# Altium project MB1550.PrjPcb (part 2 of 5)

## Sheet BOARD_PWR.SchDoc: BOARD PWR
size A4; Date: Not used; ApprovedBy: Not used; CheckedBy: Not used; Author: Not used; CompanyName: STMicroelectronics; DrawnBy: Not used; Engineer: Not used; Organization: Not used; Address1: Not used; Address2: Not used; Address3: Not used; Address4: Not used; DocumentNumber: 21; Revision: Not used; SheetNumber: 21; SheetTotal: 24
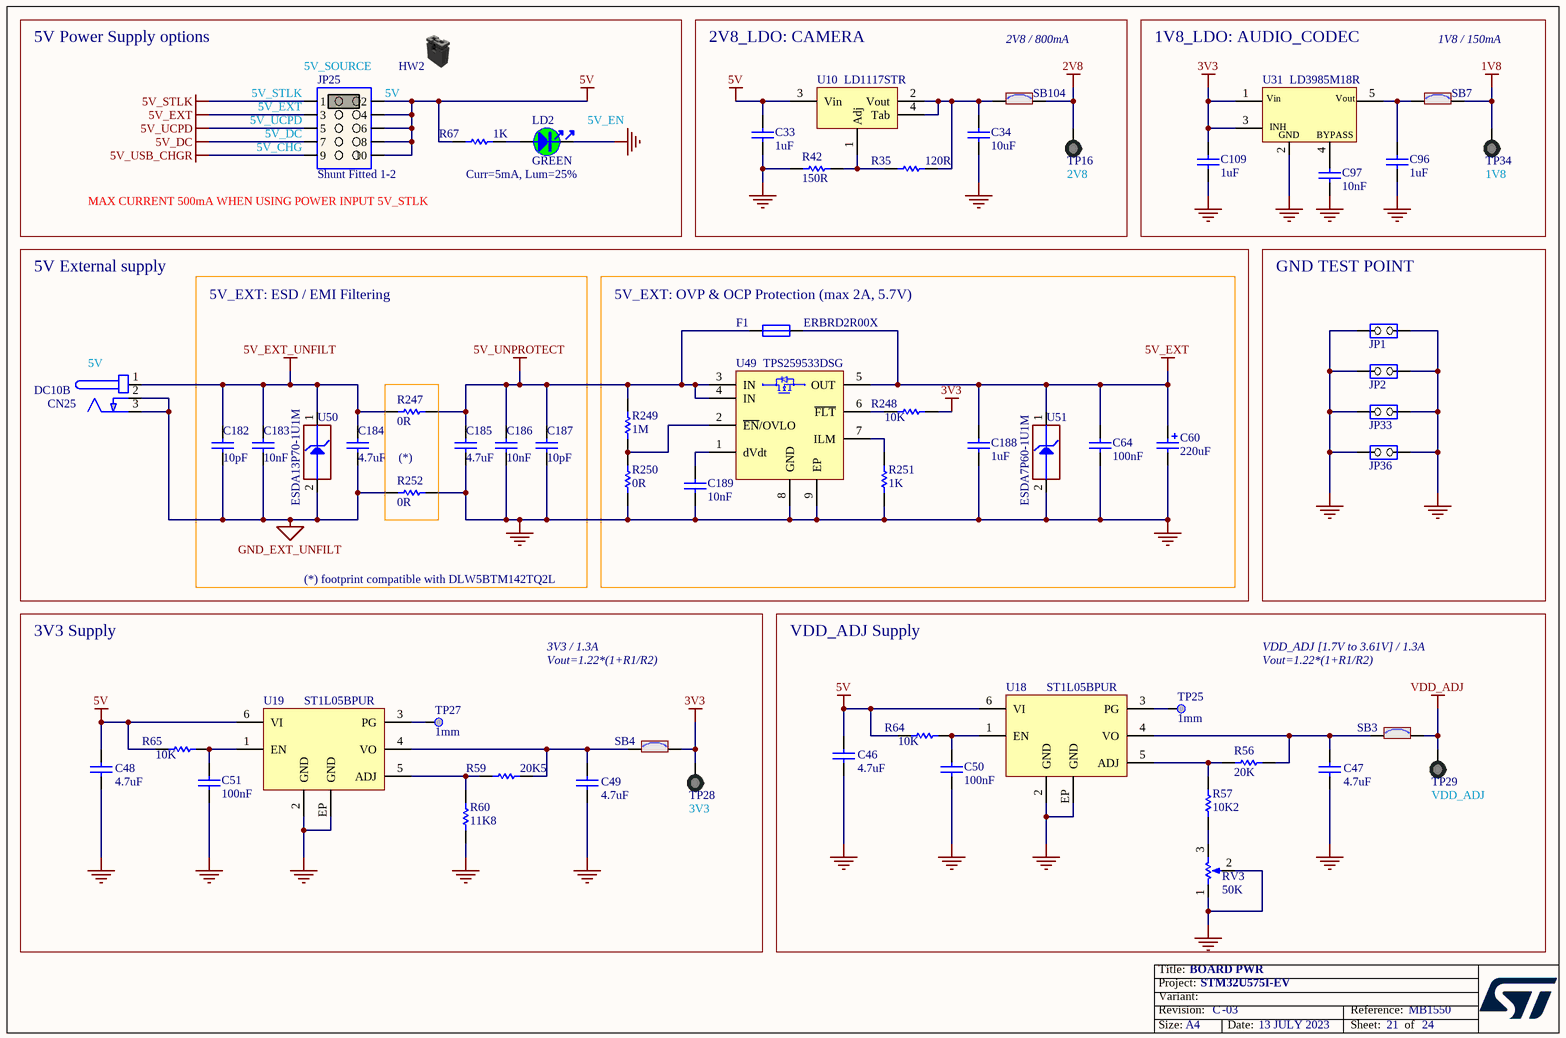
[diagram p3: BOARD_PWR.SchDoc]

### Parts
C33  value 1uF  [C0603]
C34  value 10uF  [C0402]  (hidden comment: Capacitor)
C46  value 4.7uF  [C0603]
C47  value 4.7uF  [C0603]
C48  value 4.7uF  [C0603]
C49  value 4.7uF  [C0603]
C50  value 100nF  [C0402]
C51  value 100nF  [C0402]
C60  value 220uF  [CPOL_TAJ-C_2312_H2P6]
C64  value 100nF  [C0402]
C96  value 1uF  [C0603]
C97  value 10nF  [C0402]
C109  value 1uF  [C0603]
C182  value 10pF  [C0402]  (hidden comment: Capacitor)
C183  value 10nF  [C0402]  (hidden comment: Capacitor)
C184  value 4.7uF  [C0603]  (hidden comment: Capacitor)
C185  value 4.7uF  [C0603]  (hidden comment: Capacitor)
C186  value 10nF  [C0402]  (hidden comment: Capacitor)
C187  value 10pF  [C0402]  (hidden comment: Capacitor)
C188  value 1uF  [C0603]
C189  value 10nF  [C0402]  (hidden comment: Capacitor)
CN25  value DC10B  [CON_DC-POWER-SOCKET_CLIFF_FC68149_DC10B]
F1  value ERBRD2R00X  [PTC_Panasonic_micro_chip_fuse_0402]  (hidden comment: FUSE)
HW2  (no value)  (mechanical)
JP1  Jumper_Header 2x1  [CON_SAMTEC_TSW-102-07-G-S]  (value not drawn)
JP2  Jumper_Header 2x1  [CON_SAMTEC_TSW-102-07-G-S]  (value not drawn)
JP25  value Shunt Fitted 1-2  [CON_SAMTEC_TSW-105-07-X-D]
JP33  Jumper_Header 2x1  [CON_SAMTEC_TSW-102-07-G-S]  (value not drawn)
JP36  Jumper_Header 2x1  [CON_SAMTEC_TSW-102-07-G-S]  (value not drawn)
LD2  value GREEN  [LED_0603_OSRAM_LG-Q396-PS-35_GREEN_1A2K_H0P4]
R35  value 120R  [R0603]  (hidden comment: Resistor)
R42  value 150R  [R0603]
R56  value 20K  [R0603]
R57  value 10K2  [R0603]
R59  value 20K5  [R0603]
R60  value 11K8  [R0603]
R64  value 10K  [R0603]
R65  value 10K  [R0603]
R67  value 1K  [R0603]  (hidden comment: Resistor)
R247  value 0R  [R0805]  (hidden comment: Resistor)
R248  value 10K  [R0603]
R249  value 1M  [R0402]  (hidden comment: Resistor)
R250  value 0R  [R0402]  (hidden comment: Resistor)
R251  value 1K  [R0603]  (hidden comment: Resistor)
R252  value 0R  [R0805]  (hidden comment: Resistor)
RV3  value 50K  [POT_BOURNS_3386P]  (hidden comment: POTENTIOMETER)
SB3  (no value)  [SOLDER-BRIDGE_R0603-0R]
SB4  (no value)  [SOLDER-BRIDGE_R0603-0R]
SB7  (no value)  [SOLDER-BRIDGE_R0603-0R]
SB104  (no value)  [SOLDER-BRIDGE_R0603-0R]
TP16  value 2V8  [TP_PTH_1MM_2MM]  (no BOM)
TP25  value 1mm  [TP_SMD_1MM]  (no BOM)
TP27  value 1mm  [TP_SMD_1MM]  (no BOM)
TP28  value 3V3  [TP_PTH_1MM_2MM]  (no BOM)
TP29  value VDD_ADJ  [TP_PTH_1MM_2MM]  (no BOM)
TP34  value 1V8  [TP_PTH_1MM_2MM]  (no BOM)
U10  value LD1117STR  [REG_SOT223-TAB]
U18  value ST1L05BPUR  [ICC_DFN6-EPAD_3X3_P095]
U19  value ST1L05BPUR  [ICC_DFN6-EPAD_3X3_P095]
U31  value LD3985M18R  [REG_SOT23-5L]
U49  TPS259533DSG  [ICC_WSON8-EPAD_2X2_P050]
U50  value ESDA13P70-1U1M  [ESD_QFN1610_2N_1K_2A]  (hidden comment: ESD-TRANSIL)
U51  value ESDA7P60-1U1M  [ESD_QFN2_1P6X1_P125]  (hidden comment: ESD-TRANSIL)

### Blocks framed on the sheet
5V Power Supply options: HW2 JP25 LD2 R67
2V8_LDO: CAMERA: C33 C34 R35 R42 SB104 TP16 U10
1V8_LDO: AUDIO_CODEC: C96 C97 C109 SB7 TP34 U31
5V External supply: CN25
5V_EXT: ESD / EMI Filtering: C182-C187 U50
5V_EXT: OVP & OCP Protection (max 2A, 5.7V): C60 C64 C188 C189 F1 R248-R251 U49 U51
GND TEST POINT: JP1 JP2 JP33 JP36
(*): R247 R252
3V3 Supply: C48 C49 C51 R59 R60 R65 SB4 TP27 TP28 U19
VDD_ADJ Supply: C46 C47 C50 R56 R57 R64 RV3 SB3 TP25 TP29 U18

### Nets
1V8: SB7.2 TP34.1
2V8: SB104.2 TP16.1
3V3: C109.2 R248.2 SB4.2 TP28.1 U31.1(Vin) U31.3(CE)
5V: C33.2 C46.2 C48.2 JP25.2 JP25.4 JP25.6 JP25.8 JP25.10 R64.1 R65.1 R67.1 U10.3(Vin) U18.6(VI) U19.6(VI)
5V_DC: JP25.7
5V_EXT: C60.1 C64.1 C188.2 F1.2 JP25.3 U49.5(OUT) U51.1(IO1)
5V_EXT_UNFILT: C182.2 C183.2 C184.2 CN25.1 R247.1 U50.1(IO1)
5V_STLK: JP25.1
5V_UCPD: JP25.5
5V_UNPROTECT: C185.2 C186.2 C187.2 F1.1 R247.2 R249.2 U49.3(IN) U49.4(IN)
5V_USB_CHGR: JP25.9
GND: C33.1 C34.1 C46.1 C47.1 C48.1 C49.1 C50.2 C51.2 C60.2 C64.2 C96.1 C97.1 C109.1 C185.1 C186.1 C187.1 C188.1 C189.1 JP1.1(COMMON) JP1.2(NO) JP2.1(COMMON) JP2.2(NO) JP33.1(COMMON) JP33.2(NO) JP36.1(COMMON) JP36.2(NO) LD2.2 R42.1 R60.1 R250.1 R251.1 R252.2 RV3.1(BOT) RV3.2(TAP) U18.2(GND) U18.EP(GND) U19.2(GND) U19.EP(GND) U31.2(GND) U49.8(GND) U49.9(EP) U51.2(GND)
GND_EXT_UNFILT: C182.1 C183.1 C184.1 CN25.2 CN25.3 R252.1 U50.2(GND)
VDD_ADJ: SB3.2 TP29.1
NetC34_2: C34.2 R35.2 SB104.1 U10.2(Vout) U10.4(Tab)
NetC47_2: C47.2 R56.2 SB3.1 U18.4(VO)
NetC49_2: C49.2 R59.2 SB4.1 U19.4(VO)
NetC50_1: C50.1 R64.2 U18.1(EN)
NetC51_1: C51.1 R65.2 U19.1(EN)
NetC96_2: C96.2 SB7.1 U31.5(Vout)
NetC97_2: C97.2 U31.4(BYPASS)
NetC189_2: C189.2 U49.1(dVdt)
NetLD2_1: LD2.1 R67.2
NetR35_1: R35.1 R42.2 U10.1(Adj)
NetR56_1: R56.1 R57.2 U18.5(ADJ)
NetR57_1: R57.1 RV3.3(TOP)
NetR59_1: R59.1 R60.2 U19.5(ADJ)
NetR248_1: R248.1 U49.6(~{FLT})
NetR249_1: R249.1 R250.2 U49.2(~{EN}/OVLO)
NetR251_2: R251.2 U49.7(ILM)
NetTP25_1: TP25.1 U18.3(PG)
NetTP27_1: TP27.1 U19.3(PG)

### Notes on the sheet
- 2V8 / 800mA
- 1V8 / 150mA
- (near JP25) 5V_STLK
- (near JP25) 5V_EXT
- (near JP25) 5V_SOURCE
- (near JP25) 5V
- (near JP25) 5V_UCPD
- (near JP25) 5V_CHG
- (near JP25) 5V_DC
- Curr=5mA, Lum=25%
- (near LD2) 5V_EN
- (near JP25) MAX CURRENT 500mA WHEN USING POWER INPUT 5V_STLK
- (near CN25) 5V
- (*) footprint compatible with DLW5BTM142TQ2L
- 3V3 / 1.3A
- VDD_ADJ [1.7V to 3.61V] / 1.3A
- Vout=1.22*(1+R1/R2)

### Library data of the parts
C33 C96 C109 C188 = MCD-00010: Capacitor, MLCC, 1uF, 16V, X5R, 10%, 0603, T=0,8mm; Manufacturer_Part_Number: CC0603KRX5R7BB105; Manufacturer: YAGEO; Provided_By: Subcon; Initial_Board_Reference: MB1274
C34 = MCD-01355: Capacitor, MLCC, 10uF, 4V, X5R, 20%, 0402, T=0,5mm; Manufacturer_Part_Number: GRM155R60G106ME44; Manufacturer: MURATA; ECCN_US: EAR99; ECCN_EU: NEC; Provided_By: Subcon; Initial_Board_Reference: MB1372
C46-C49 = MCD-00009: Capacitor, MLCC, 4.7uF, 16V, X5R, 10%, 0603, T=0.8mm; Manufacturer_Part_Number: CC0603KRX5R7BB475; Manufacturer: YAGEO; ECCN_US: EAR99; ECCN_EU: NEC; Provided_By: SUBCO
C50 C51 C64 = MCD-00006: Capacitor, MLCC, 100nF, 16V, X7R, 10%, 0402, T=0.5mm; Manufacturer_Part_Number: CC0402KRX7R7BB104; Manufacturer: YAGEO; Alternate_Manufacturer_Part_Number: GCM155R71C104KA55D; Alternate_Manufacturer: MURATA; Provided_By: SUBCO; ECCN_US: EAR99; ECCN_EU: NEC
C60 = MCD-00142: Capacitor, Tantalum, 220uF, 10V, 10%, TypeC; Manufacturer_Part_Number: TAJC227K010R; Manufacturer: AVX; Provided_By: Subcon; ECCN_US: EAR99; ECCN_EU: NEC; Initial_Board_Reference: MB1262
C97 = MCD-00011: Capacitor, MLCC, 10nF, 16V, X7R, 10%, 0402, T=0.5mm; Manufacturer_Part_Number: CC0402KRX7R7BB103; Manufacturer: YAGEO; Provided_By: Subcon; Initial_Board_Reference: MB1274
C182 C187 = MCD-00015: Capacitor, MLCC, 10pF, 50V, NPO, +/-5%, 0402, T=0,5mm; Manufacturer_Part_Number: CC0402JRNPO9BN100; Manufacturer: YAGEO; Part_Preference: Recommended
C183 C186 = MCD-02198: Capacitor, MLCC, 10nF, 50V ,X7R, +/-10%, 0402, T=0.5mm; Manufacturer_Part_Number: CC0402KRX7R9BB103; Manufacturer: YAGEO; Alternate_Manufacturer_Part_Number: UMF105B7103KVHF; Alternate_Manufacturer: TAIYO YUDEN; Part_Preference: Recommended; Order_Code_RS: 6169644
C184 C185 = MCD-02196: Capacitor, MLCC, 4.7uF, 25V, X5R, +/-10%, 0603, T=0,8mm; Manufacturer_Part_Number: C1608X5R1E475K080AC; Manufacturer: TDK; Alternate_Manufacturer_Part_Number: TMK107BBJ475KA-T; Alternate_Manufacturer: TAIYO YUDEN; Part_Preference: Recommended; Order_Code_RS: 9159158
C189 = MCD-00011: Capacitor, MLCC, 10nF, 16V, X7R, +/-10%, 0402, T=0.5mm; Manufacturer_Part_Number: CC0402KRX7R7BB103; Manufacturer: YAGEO; Part_Preference: Recommended; Order_Code_RS: 669-8688
CN25 = MCD-00173: DC-Power-Jack, 2.5mm, 5A, RA, TH; Manufacturer: CLIFF; Part_Type: Connector; Provided_By: Subcon; Initial_Board_Reference: MB1265
F1 = MCD-02197: Micro Chip Fuse, Fast Acting, 2A, 53mOhm, 32V Rated Voltage; Part_Type: Misc; Manufacturer: PANASONIC; Part_Preference: Recommended; Order_Code_RS: 7594751
HW2 = MCD-00043: SHUNT 2.54mm BLACK; Part_Type: Mechanical; Manufacturer_Part_Number: SNT-100-BK-G; Manufacturer: SAMTEC; Provided_By: Subcon; Initial_Board_Reference: MB1274
JP1 JP2 JP33 JP36 = MCD-00045: Header, 2x1, 2,54mm, VR, TH, Height 5.84mm/2.54mm; Part_Type: Connector; Manufacturer_Part_Number: TSW-102-07-x-S; Manufacturer: SAMTEC; Value: Shunt not fitted; Provided_By: Subcon; Initial_Board_Reference: MB1274; Remark: 3D KO: BZ: 40098
JP25 = MCD-01203: Header, 5x2, 2,54mm, VR, TH, Height 5.84mm/2.54mm - Shunt Fitted 1-2; Part_Type: Connector; Manufacturer_Part_Number: TSW-105-07-x-D; Manufacturer: SAMTEC; Provided_By: Subcon; Initial_Board_Reference: Mb1372
LD2 = MCD-00588: LED Green, 0603 SMD, Forward Voltage Typ=2V, Max=2.5V; Part_Type: Display; Manufacturer_Part_Number: LG Q396-PS-35; Manufacturer: OSRAM OPTO SEMICONDUCTORS; Alternate_Manufacturer_Part_Number: VLMTG1300-GS08; Alternate_Manufacturer: VISHAY SEMICONDUCTOR OPTO DIVISION; Provided_By: Subcon; Initial_Board_Reference: MB1331
R35 = MCD-00338: Resistor,120R,0603,1%,1/10W; Manufacturer_Part_Number: RC0603FR-07120RL; Manufacturer: YAGEO; BMS_Part_Number: 9129734; ECCN_US: EAR99; ECCN_EU: NEC; Provided_By: SUBCO
R42 = MCD-00394: Resistor,150,0603,1%,1/10W; Manufacturer_Part_Number: RC0603FR-07150RL; Manufacturer: YAGEO; ECCN_US: EAR99; ECCN_EU: NEC; Provided_By: SUBCO
R56 = MCD-00422: Resistor,20K,0603,1%,1/10W; Manufacturer_Part_Number: RC0603FR-0720KL; Manufacturer: YAGEO; Provided_By: Subcon
R57 = MCD-01155: Resistor,10K2,0603,1%,1/10W; Manufacturer_Part_Number: RC0603FR-0710K2L; Manufacturer: YAGEO; Provided_By: Subcon; Initial_Board_Reference: MB1372
R59 = MCD-01149: Resistor,20K5,0603,1%,1/10W; Manufacturer_Part_Number: RC0603FR-0720K5L; Manufacturer: YAGEO; Provided_By: Subcon; Initial_Board_Reference: MB1372
R60 = MCD-00244: Resistor,11K8,0603,1%,1/10W; Manufacturer_Part_Number: RC0603FR-0711K8L; Manufacturer: YAGEO; Provided_By: Subcon; Initial_Board_Reference: MB1319
R64 R65 R248 = MCD-00220: Resistor,10K,0603,1%,1/10W; Manufacturer_Part_Number: RC0603FR-0710KL; Manufacturer: YAGEO; Provided_By: Subcon; Initial_Board_Reference: MB1319
R67 R251 = MCD-00070: Resistor,1K,0603,1%,1/10W; Manufacturer_Part_Number: RC0603FR-071KL; Manufacturer: YAGEO; ECCN_US: EAR99; ECCN_EU: NEC; Provided_By: SUBCO
R247 R252 = MCD-00179: Resistor,0R,0805,5%?1/8W; Manufacturer_Part_Number: RC0805JR-070RL; Manufacturer: YAGEO; Part_Preference: Recommended
R249 = MCD-00182: Resistor,1M,0402,1%,1/16W; Manufacturer_Part_Number: RC0402FR-071ML; Manufacturer: YAGEO; BMS_Part_Number: 9131778; Part_Preference: Recommended; Order_Code_RS: 618-6194
R250 = MCD-00052: Resistor,0R,0402,5%,1/16W; Manufacturer_Part_Number: RC0402JR-070RL; Manufacturer: YAGEO; Part_Preference: Recommended; Order_Code_RS: 618-5804
RV3 = MCD-01156: Trimmer, 50K, 3386P, +/-10%, 1/2W, T=10.41mm; Part_Type: Resistor; Manufacturer_Part_Number: 3386P-1-503TLF; Manufacturer: BOURNS; Part_Preference: Recommended; Order_Code_RS: 167-3478
SB3 SB4 SB7 SB104 = MCD-00071: Solder Bridge ON; Part_Type: Mechanical; Provided_By: Subcon; Initial_Board_Reference: MB1274
TP16 TP28 TP29 TP34 = MCD-01506: Test Point trought hole 1mm/2mm; Part_Type: Mechanical; Initial_Board_Reference: MB1372; Item Type: Item; Path: ws/MCD_ApplicationBoards/Lists/MCDPARTSdatabase
TP25 TP27 = MCD-00074: Test Point 1mm; Part_Type: Mechanical; Initial_Board_Reference: MB1274
U10 = MCD-00721: LDO Voltage Regulator, Adjustable, 15V in, 1.1V drop, 1.25V to 15V/0.8A out, SOT-223-3; Part_Type: IC; Manufacturer: STMICROELECTRONICS; BMS_Part_Number: 9176132; ECCN_US: EAR99; ECCN_EU: NEC; Provided_By: SUBCO with ST control
U18 U19 = MCD-00581: LDO Linear Voltage Regulator IC Positive Adjustable 1 Output Adjustable 1.3A 6-DFN (3x3); Manufacturer: STMICROELECTRONICS; ECCN_US: EAR99; ECCN_EU: NEC; Provided_By: Subcon; Initial_Board_Reference: MB1331
U31 = MCD-00078: Ultra low drop-low noise BiCMOS voltage, regulators low ESR capacitors compatible; Manufacturer: STMICROELECTRONICS; Part_Type: IC; ECCN_US: EAR99; ECCN_EU: NEC; Provided_By: Subcon; Initial_Board_Reference: MB1274
U49 = MCD-02194: eFuse with Fast Overvoltage Protection 2.7V to 18V 4A 34mOhm 8-Pin WSON; Part_Type: IC; Manufacturer_Part_Number: TPS259533DSGR; Manufacturer: TEXAS INSTRUMENTS; Alternate_Manufacturer_Part_Number: TPS259533DSGT; Part_Preference: Recommended
U50 = MCD-02195: Diode, High power transient voltage suppressor, 13V breakdown; Manufacturer: STMICROELECTRONICS; Manufacturer_HQ_COO: EU; Part_Preference: Recommended; Order_Code_RS: 1106380
U51 = MCD-00251: High power transient voltage suppressor, 7V breakdown; Part_Type: Diode; Manufacturer: STMICROELECTRONICS; BMS_Part_Number: 9179042; Manufacturer_HQ_COO: EU; Part_Preference: Recommended

## Sheet Extension_Connector.SchDoc: EXTENSION CONNECTORS
size A4; Date: Not used; ApprovedBy: Not used; CheckedBy: Not used; Author: Not used; CompanyName: STMicroelectronics; DrawnBy: Not used; Engineer: Not used; Organization: Not used; Address1: Not used; Address2: Not used; Address3: Not used; Address4: Not used; DocumentNumber: 24; Revision: Not used; SheetNumber: 24; SheetTotal: 24
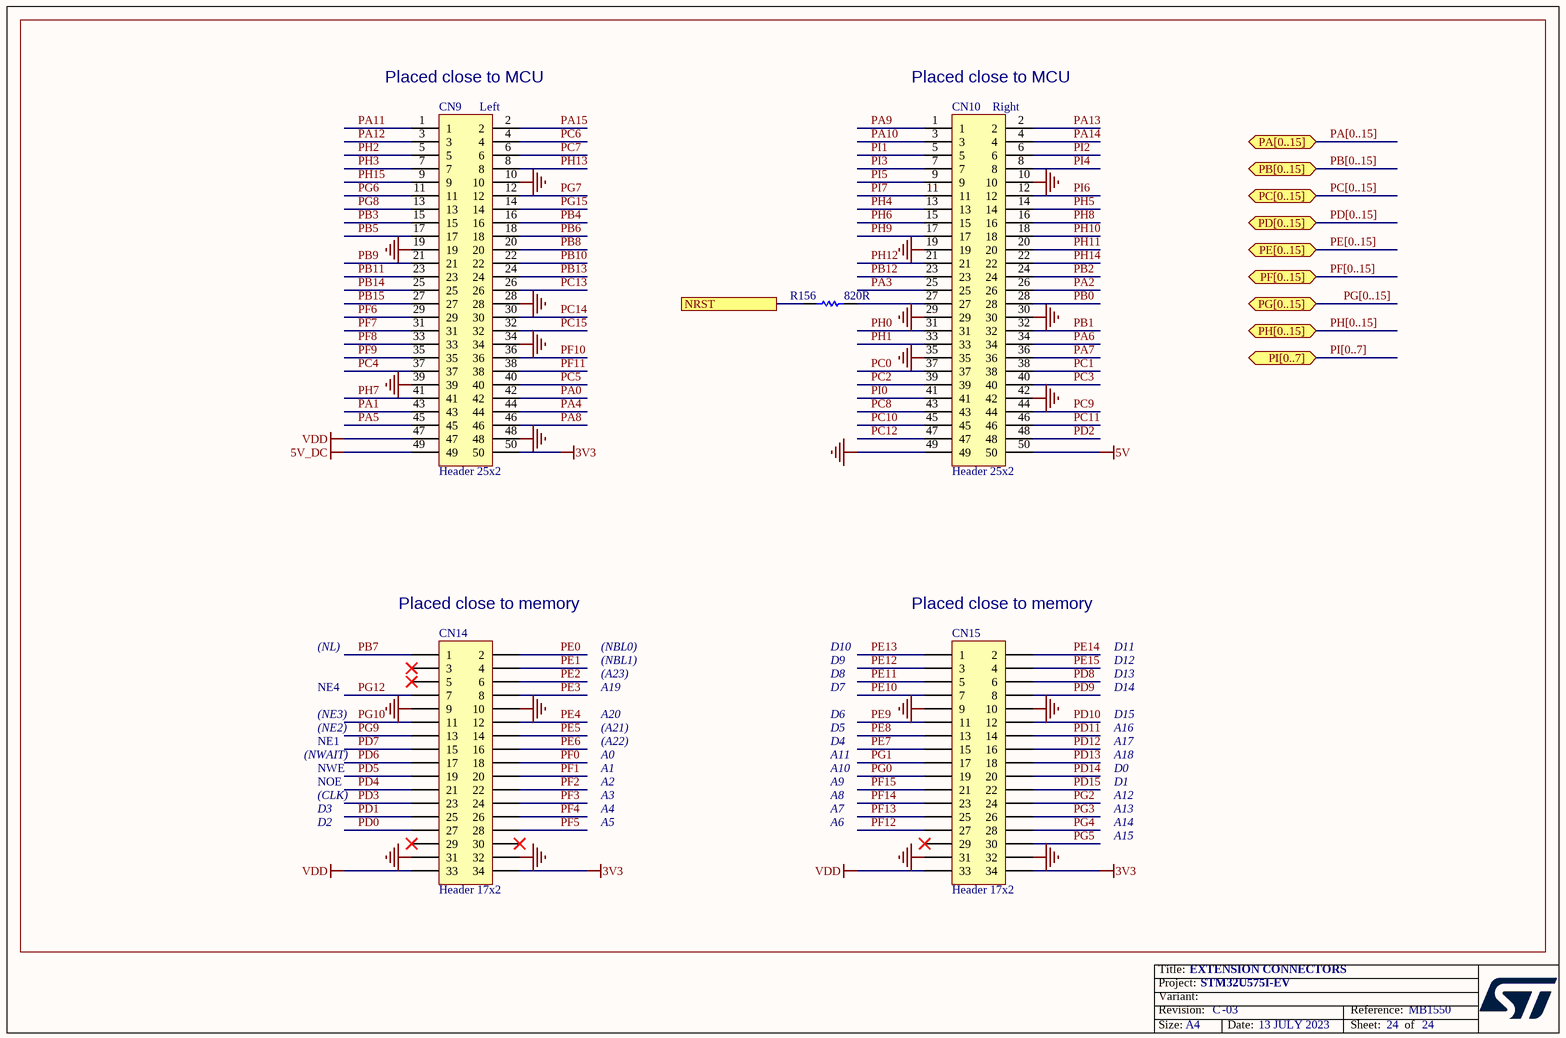
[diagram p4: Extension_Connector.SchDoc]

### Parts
CN9  Header 25x2  [CON_SAMTEC_FTR-125-03-L-D-LC]
CN10  Header 25x2  [CON_SAMTEC_FTR-125-03-L-D-LC]
CN14  Header 17x2  [CON_SAMTEC_FTR-117-03-L-D-LC]
CN15  Header 17x2  [CON_SAMTEC_FTR-117-03-L-D-LC]
R156  value 820R  [R0603]

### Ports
NRST, PA[0..15] (bidir), PB[0..15] (bidir), PC[0..15] (bidir), PD[0..15] (bidir), PE[0..15] (bidir), PF[0..15] (bidir), PG[0..15] (bidir), PH[0..15] (bidir), PI[0..7] (bidir)

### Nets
3V3: CN9.50 CN14.34 CN15.34
5V: CN10.50
5V_DC: CN9.49
GND: CN9.10 CN9.19 CN9.28 CN9.34 CN9.39 CN9.48 CN10.10 CN10.19 CN10.29 CN10.30 CN10.35 CN10.42 CN10.49 CN14.9 CN14.10 CN14.31 CN14.32 CN15.9 CN15.10 CN15.31 CN15.32
VDD: CN9.47 CN14.33 CN15.33
NRST: R156.1 ; port NRST
PA0: CN9.42
PA1: CN9.43
PA2: CN10.26
PA3: CN10.25
PA4: CN9.44
PA5: CN9.45
PA6: CN10.34
PA7: CN10.36
PA8: CN9.46
PA9: CN10.1
PA10: CN10.3
PA11: CN9.1
PA12: CN9.3
PA13: CN10.2  [project net JTMS_SWDIO]
PA14: CN10.4  [project net JTCK_SWCLK]
PA15: CN9.2
PB0: CN10.28
PB1: CN10.32
PB2: CN10.24
PB3: CN9.15
PB4: CN9.16
PB5: CN9.17
PB6: CN9.18
PB7: CN14.1
PB8: CN9.20
PB9: CN9.21
PB10: CN9.22
PB11: CN9.23
PB12: CN10.23
PB13: CN9.24
PB14: CN9.25
PB15: CN9.27
PC0: CN10.37
PC1: CN10.38
PC2: CN10.39
PC3: CN10.40
PC4: CN9.37
PC5: CN9.40
PC6: CN9.4
PC7: CN9.6
PC8: CN10.43
PC9: CN10.44
PC10: CN10.45
PC11: CN10.46
PC12: CN10.47
PC13: CN9.26
PC14: CN9.30
PC15: CN9.32
PD0: CN14.27
PD1: CN14.25
PD2: CN10.48
PD3: CN14.23
PD4: CN14.21
PD5: CN14.19
PD6: CN14.17
PD7: CN14.15
PD8: CN15.6
PD9: CN15.8
PD10: CN15.12
PD11: CN15.14
PD12: CN15.16
PD13: CN15.18
PD14: CN15.20
PD15: CN15.22
PE0: CN14.2
PE1: CN14.4
PE2: CN14.6
PE3: CN14.8
PE4: CN14.12
PE5: CN14.14
PE6: CN14.16
PE7: CN15.15
PE8: CN15.13
PE9: CN15.11
PE10: CN15.7
PE11: CN15.5
PE12: CN15.3
PE13: CN15.1
PE14: CN15.2
PE15: CN15.4
PF0: CN14.18
PF1: CN14.20
PF2: CN14.22
PF3: CN14.24
PF4: CN14.26
PF5: CN14.28
PF6: CN9.29
PF7: CN9.31
PF8: CN9.33
PF9: CN9.35
PF10: CN9.36
PF11: CN9.38
PF12: CN15.27
PF13: CN15.25
PF14: CN15.23
PF15: CN15.21
PG0: CN15.19
PG1: CN15.17
PG2: CN15.24
PG3: CN15.26
PG4: CN15.28
PG5: CN15.30
PG6: CN9.11
PG7: CN9.12
PG8: CN9.13
PG9: CN14.13
PG10: CN14.11
PG12: CN14.7
PG15: CN9.14
PH0: CN10.31
PH1: CN10.33
PH2: CN9.5
PH3: CN9.7
PH4: CN10.13
PH5: CN10.14
PH6: CN10.15
PH7: CN9.41
PH8: CN10.16
PH9: CN10.17  [project net DCMI_D0]
PH10: CN10.18  [project net DCMI_D1]
PH11: CN10.20  [project net DCMI_D2]
PH12: CN10.21  [project net DCMI_D3]
PH13: CN9.8
PH14: CN10.22  [project net DCMI_D4]
PH15: CN9.9
PI0: CN10.41
PI1: CN10.5
PI2: CN10.6
PI3: CN10.7
PI4: CN10.8  [project net DCMI_D5]
PI5: CN10.9
PI6: CN10.12  [project net DCMI_D6]
PI7: CN10.11  [project net DCMI_D7]
NetCN10_27: CN10.27 R156.2

Not connected (* = marked no-connect by the designer): CN14 3* 5* 29* 30*; CN15 29*

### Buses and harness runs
bus PA[0..15] = port PA[0..15]
bus PB[0..15] = port PB[0..15]
bus PC[0..15] = port PC[0..15]
bus PD[0..15] = port PD[0..15]
bus PE[0..15] = port PE[0..15]
bus PF[0..15] = port PF[0..15]
bus PG[0..15] = port PG[0..15]
bus PH[0..15] = port PH[0..15]
bus PI[0..7] = port PI[0..7]

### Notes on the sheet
- (near CN9) Placed close to MCU
- (near CN9) Left
- (near CN10) Placed close to MCU
- (near CN10) Right
- (NL)
- (near CN14) Placed close to memory
- (NBL0)
- D10
- (near CN15) Placed close to memory
- D11
- (NE3)
- NE4
- A19
- A20
- (A23)
- (NBL1)
- D6
- D7
- D8
- D9
- D12
- D13
- D14
- D15
- (NWAIT)
- NOE
- NWE
- NE1
- (NE2)
- A0
- A1
- A2
- (A21)
- (A22)
- A9
- A10
- A11
- D4
- D5
- A16
- A17
- A18
- D0
- D1
- D2
- D3
- (CLK)
- A3
- A4
- A5
- A6
- A7
- A8
- A12
- A13
- A14
- A15

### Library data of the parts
CN9 CN10 = MCD-02111: Header 25x2, 1.27mm, VR, CMS, Height 7.24mm; Part_Type: Connector; Manufacturer_Part_Number: FTR-125-03-L-D-LC; Manufacturer: SAMTEC; Provided_By: SUBCO
CN14 CN15 = MCD-01344: Header 17x2, 1.27mm, VR, CMS, Height 7.24mm, locking-clip; Part_Type: Connector; Manufacturer_Part_Number: FTR-117-03-L-D-LC; Manufacturer: SAMTEC; Provided_By: Subcon; Initial_Board_Reference: MB1372
R156 = MCD-00528: Resistor,820R,0603,1%,1/10W; Manufacturer_Part_Number: RC0603FR-07820RL; Manufacturer: YAGEO; Provided_By: Subcon

## Sheet FDCAN_RS232.SchDoc: FDCAN & RS232
size A4; Date: Not used; ApprovedBy: Not used; CheckedBy: Not used; Author: Not used; CompanyName: STMicroelectronics; DrawnBy: Not used; Engineer: Not used; Organization: Not used; Address1: Not used; Address2: Not used; Address3: Not used; Address4: Not used; DocumentNumber: 14; Revision: Not used; SheetNumber: 14; SheetTotal: 24
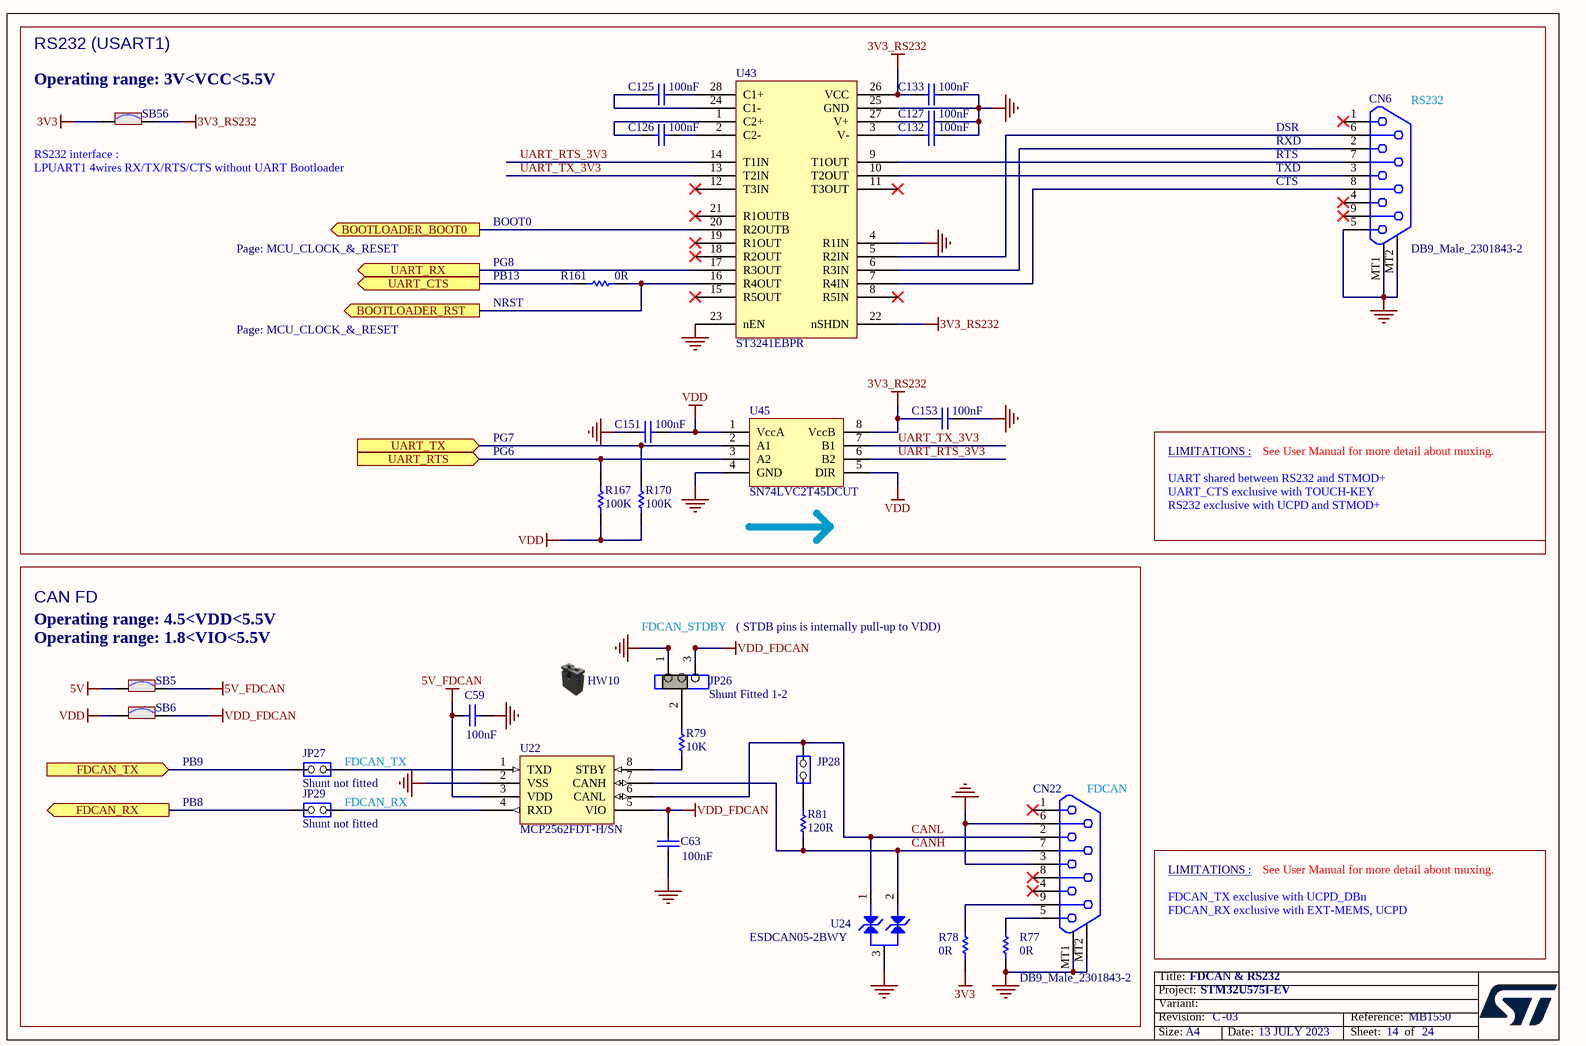
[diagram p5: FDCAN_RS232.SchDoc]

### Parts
C59  value 100nF  [C0402]
C63  value 100nF  [C0402]
C125  value 100nF  [C0402]
C126  value 100nF  [C0402]
C127  value 100nF  [C0402]
C132  value 100nF  [C0402]
C133  value 100nF  [C0402]
C151  value 100nF  [C0402]
C153  value 100nF  [C0402]
CN6  value DB9_Male_2301843-2  [CON_DB9-MALE_TYCO_2301843-2]  (hidden comment: DB9_Header_male_2301843-2)
CN22  value DB9_Male_2301843-2  [CON_DB9-MALE_TYCO_2301843-2]  (hidden comment: DB9_Header_male_2301843-2)
HW10  (no value)  (mechanical)
JP26  value Shunt Fitted 1-2  [CON_SAMTEC_TSW-103-07-F-S]
JP27  value Shunt not fitted  [CON_SAMTEC_TSW-102-07-G-S]
JP28  (no value)  [CON_SAMTEC_TSW-102-07-G-S]
JP29  value Shunt not fitted  [CON_SAMTEC_TSW-102-07-G-S]
R77  value 0R  [R0603]
R78  value 0R  [R0603]
R79  value 10K  [R0603]
R81  value 120R  [R0603]
R161  value 0R  [R0603]
R167  value 100K  [R0603]
R170  value 100K  [R0603]
SB5  (no value)  [SOLDER-BRIDGE_R0603-0R]
SB6  (no value)  [SOLDER-BRIDGE_R0603-0R]
SB56  (no value)  [SOLDER-BRIDGE_R0603-0R]
U22  value MCP2562FDT-H/SN  [ICC_SO8_5X4_P127]
U24  value ESDCAN05-2BWY  [DIO_SOT323]  (hidden comment: ESD-TRANSIL-DUAL-BIDIR)
U43  value ST3241EBPR  [ICC_SSOP28_10P2X5P3_P065]
U45  value SN74LVC2T45DCUT  [ICC_VSSOP8_DCU_R-PDSO-G8_2X2P30_P050]

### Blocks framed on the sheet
RS232 (USART1): C125-C127 C132 C133 C151 C153 CN6 R161 R167 R170 SB56 U43 U45
CAN FD: C59 C63 CN22 HW10 JP26-JP29 R77-R79 R81 SB5 SB6 U22 U24

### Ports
BOOTLOADER_BOOT0 (out), BOOTLOADER_RST (out), FDCAN_RX (out), FDCAN_TX (in), UART_CTS (out), UART_RTS (in), UART_RX (out), UART_TX (in)

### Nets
3V3: R78.1 SB56.1
3V3_RS232: C133.1 C153.1 SB56.2 U43.22(nSHDN) U43.26(VCC) U45.8(VccB)
5V: SB5.1
5V_FDCAN: C59.1 SB5.2 U22.3(VDD)
GND: C59.2 C63.2 C127.1 C132.1 C133.2 C151.1 C153.2 CN6.5 CN6.MT1 CN6.MT2 CN22.3 CN22.6 CN22.MT1 CN22.MT2 JP26.1 R77.1 U22.2(VSS) U24.3 U43.4(R1IN) U43.23(nEN) U43.25(GND) U45.4(GND)
VDD: C151.2 R167.1 R170.1 SB6.1 U45.1(VccA) U45.5(DIR)
VDD_FDCAN: C63.1 JP26.3 SB6.2 U22.5(VIO)
BOOTLOADER_BOOT0: U43.20(R2OUTB) ; port BOOTLOADER_BOOT0
BOOTLOADER_RST: R161.2 U43.16(R4OUT) ; port BOOTLOADER_RST
CANH: CN22.7 R81.1 U22.7(CANH) U24.2
CANL: CN22.2 JP28.2(NO) U22.6(CANL) U24.1
PB8: JP29.1(COMMON) ; port FDCAN_RX
PB9: JP27.1(COMMON) ; port FDCAN_TX
UART_CTS: R161.1 ; port UART_CTS
UART_RTS: R167.2 U45.3(A2) ; port UART_RTS
UART_RTS_3V3: U43.14(T1IN) U45.6(B2)
UART_RX: U43.17(R3OUT) ; port UART_RX
UART_TX: R170.2 U45.2(A1) ; port UART_TX
UART_TX_3V3: U43.13(T2IN) U45.7(B1)
NetC125_1: C125.1 U43.24(C1-)
NetC125_2: C125.2 U43.28(C1+)
NetC126_1: C126.1 U43.1(C2+)
NetC126_2: C126.2 U43.2(C2-)
NetC127_2: C127.2 U43.27(V+)
NetC132_2: C132.2 U43.3(V-)
NetCN6_2: CN6.2 U43.6(R3IN)
NetCN6_3: CN6.3 U43.10(T2OUT)
NetCN6_6: CN6.6 U43.5(R2IN)
NetCN6_7: CN6.7 U43.9(T1OUT)
NetCN6_8: CN6.8 U43.7(R4IN)
NetCN22_5: CN22.5 R77.2
NetCN22_9: CN22.9 R78.2
NetJP26_2: JP26.2 R79.2
NetJP27_2: JP27.2(NO) U22.1(TXD)
NetJP28_1: JP28.1(COMMON) R81.2
NetJP29_2: JP29.2(NO) U22.4(RXD)
NetR79_1: R79.1 U22.8(STBY)

Not connected (* = marked no-connect by the designer): CN6 1* 4* 9*; CN22 1* 4* 8*; U43 8(R5IN)* 11(T3OUT)* 12(T3IN)* 15(R5OUT)* 18(R2OUT)* 19(R1OUT)* 21(R1OUTB)*

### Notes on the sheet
- (near SB56) Operating range: 3V<VCC<5.5V
- (near CN6) RS232
- (near SB56) RS232 interface :
- (near SB56) LPUART1 4wires RX/TX/RTS/CTS without UART Bootloader
- RXD
- TXD
- CTS
- DSR
- RTS
- Page: MCU_CLOCK_&_RESET
- BOOT0
- PG8
- NRST
- PB13
- PG7
- PG6
- LIMITATIONS :
- See User Manual for more detail about muxing.
- UART_CTS exclusive with TOUCH-KEY
- UART shared between RS232 and STMOD+
- RS232 exclusive with UCPD and STMOD+
- (near SB5) Operating range: 4.5<VDD<5.5V
  Operating range: 1.8<VIO<5.5V
- (near JP26) FDCAN_STDBY
- ( STDB pins is internally pull-up to VDD)
- PB9
- (near JP27) FDCAN_TX
- (near CN22) FDCAN
- PB8
- FDCAN_RX
- FDCAN_RX exclusive with EXT-MEMS, UCPD
- FDCAN_TX exclusive with UCPD_DBn

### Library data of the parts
C59 C63 C125-C127 C132 C133 C151 C153 = MCD-00006: as C50 on sheet BOARD_PWR
CN6 CN22 = MCD-01978: DB9_Male, RA, TH, height 13.575mm/3.8mm; Part_Type: Connector; Manufacturer: TYCO; ECCN_US: EAR99; ECCN_EU: NEC; Provided_By: SUBCO
HW10 = MCD-00043: SHUNT 2.54mm BLACK; Manufacturer_Part_Number: SNT-100-BK-G; Manufacturer: SAMTEC; Part_Type: Mechanical; Provided_By: Subcon; Initial_Board_Reference: MB1274
JP26 = MCD-00684: Header, 3x1, 2,54mm, VR, TH, Height 5.84mm/2.54mm - Shunt Fitted 1-2 by default; Part_Type: Connector; Manufacturer_Part_Number: TSW-103-07-F-S; Manufacturer: SAMTEC; Provided_By: Subcon; Initial_Board_Reference: MB1331
JP27 JP29 = MCD-00045: Header, 2x1, 2,54mm, VR, TH, Height 5.84mm/2.54mm; Part_Type: Connector; Manufacturer_Part_Number: TSW-102-07-x-S; Manufacturer: SAMTEC; Provided_By: Subcon; Initial_Board_Reference: MB1274
JP28 = MCD-00045: Header, 2x1, 2,54mm, VR, TH, Height 5.84mm/2.54mm; Manufacturer_Part_Number: TSW-102-07-x-S; Manufacturer: SAMTEC; Part_Type: Connector; Value: Shunt not fitted; Provided_By: Subcon; Initial_Board_Reference: MB1274
R77 R78 R161 = MCD-00056: Resistor,0R,0603,5%,1/10W; Manufacturer_Part_Number: RC0603JR-070RL; Manufacturer: YAGEO; Provided_By: subcon; Initial_Board_Reference: MB1274
R79 = MCD-00220: as R64 on sheet BOARD_PWR
R81 = MCD-00338: Resistor,120R,0603,1%,1/10W; Manufacturer_Part_Number: RC0603FR-07120RL; Manufacturer: YAGEO; Provided_By: Subcon
R167 R170 = MCD-00223: Resistor,100K,0603,1%,1/10W; Manufacturer_Part_Number: RC0603FR-07100KL; Manufacturer: YAGEO; Provided_By: Subcon; Initial_Board_Reference: MB1319
SB5 SB6 SB56 = MCD-00071: as SB3 on sheet BOARD_PWR
U22 = MCD-00129: High-Speed CAN Flexible Data Rate Transceiver; Manufacturer: MICROCHIP; Part_Type: IC; Provided_By: Subcon; ECCN_US: EAR99; ECCN_EU: NEC; Initial_Board_Reference: MB1262
U24 = MCD-01358: Automotive dual-line Transil, transient voltage suppressor (TVS) for CAN bus 36V. Compliant with interfaces in automotive: CAN-FD, LIN, FlexRay, MOST, SENT, USB; Part_Type: Diode; Manufacturer: STMICROELECTRONICS; ECCN_US: EAR99; ECCN_EU: NEC; Provided_By: Subcon; Initial_Board_Reference: MB1372
U43 = MCD-00152: RS-232 transceiver with auto-power-down; Part_Type: IC; Manufacturer: STMICROELECTRONICS; Provided_By: Subcon; ECCN_US: EAR99; ECCN_EU: NEC; Initial_Board_Reference: MB1262
U45 = MCD-00264: Dual bit dual supply bus transceiver; Part_Type: IC; Manufacturer: TEXAS INSTRUMENTS; ECCN_US: EAR99; ECCN_EU: NEC; Provided_By: Subcon; Initial_Board_Reference: MB1319

## Sheet JTAG_TRACE.SchDoc: JTAG & TRACE
size A4; Date: Not used; ApprovedBy: Not used; CheckedBy: Not used; Author: Not used; CompanyName: STMicroelectronics; DrawnBy: Not used; Engineer: Not used; Organization: Not used; Address1: Not used; Address2: Not used; Address3: Not used; Address4: Not used; DocumentNumber: 22; Revision: Not used; SheetNumber: 22; SheetTotal: 24
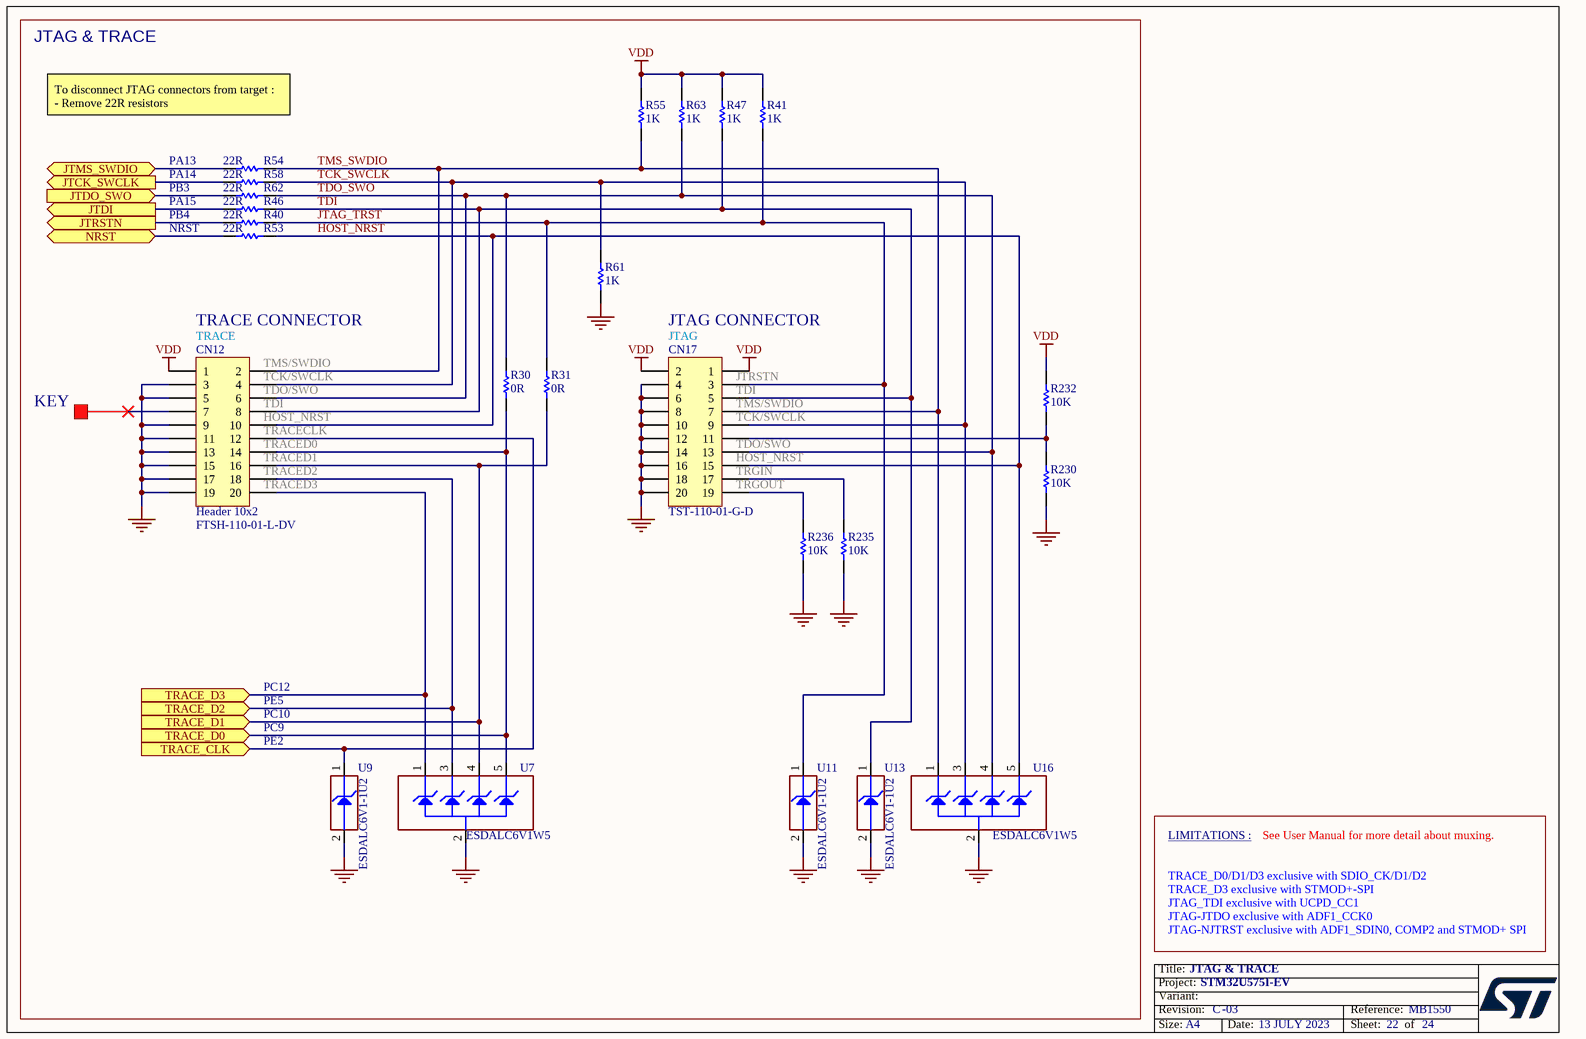
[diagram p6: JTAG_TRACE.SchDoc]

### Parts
CN12  value Header 10x2  [CON_SAMTEC_FTSH-110-01-L-DV]
CN17  value TST-110-01-G-D  [CON_CVILUX_CH87-20-2-V-1-00]
R30  value 0R  [R0603]
R31  value 0R  [R0603]
R40  value 22R  [R0603]
R41  value 1K  [R0603]
R46  value 22R  [R0603]
R47  value 1K  [R0603]
R53  value 22R  [R0603]
R54  value 22R  [R0603]
R55  value 1K  [R0603]
R58  value 22R  [R0603]
R61  value 1K  [R0603]
R62  value 22R  [R0603]
R63  value 1K  [R0603]
R230  value 10K  [R0603]
R232  value 10K  [R0603]
R235  value 10K  [R0603]
R236  value 10K  [R0603]
U7  value ESDALC6V1W5  [ESD_SOT323-5L]
U9  value ESDALC6V1-1U2  [ESD_ST0201]
U11  value ESDALC6V1-1U2  [ESD_ST0201]
U13  value ESDALC6V1-1U2  [ESD_ST0201]
U16  value ESDALC6V1W5  [ESD_SOT323-5L]

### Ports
JTCK_SWCLK (out), JTDI (out), JTDO_SWO (in), JTMS_SWDIO (bidir), JTRSTN (out), NRST (bidir), TRACE_CLK (in), TRACE_D0 (in), TRACE_D1 (in), TRACE_D2 (in), TRACE_D3 (in)

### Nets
GND: CN12.3 CN12.5 CN12.9 CN12.11 CN12.13 CN12.15 CN12.17 CN12.19 CN17.4 CN17.6 CN17.8 CN17.10 CN17.12 CN17.14 CN17.16 CN17.18 CN17.20 R61.1 R230.1 R235.1 R236.1 U7.2(GND) U9.2(GND) U11.2(GND) U13.2(GND) U16.2(GND)
VDD: CN12.1 CN17.1 CN17.2 R41.2 R47.2 R55.2 R63.2 R232.2
HOST_NRST: CN12.10 CN17.15 R53.1 U16.5(IO4)
JTAG_TRST: CN17.3 R31.2 R40.1 R41.1 U11.1(IO1)
JTCK_SWCLK: R58.2 ; port JTCK_SWCLK
JTDI: R46.2 ; port JTDI
JTDO_SWO: R62.2 ; port JTDO_SWO
JTMS_SWDIO: R54.2 ; port JTMS_SWDIO
JTRSTN: R40.2 ; port JTRSTN
NRST: R53.2 ; port NRST
TCK_SWCLK: CN12.4 CN17.9 R58.1 R61.2 U16.3(IO2)
TDI: CN12.8 CN17.5 R46.1 R47.1 U13.1(IO1)
TDO_SWO: CN12.6 CN17.13 R30.2 R62.1 R63.1 U16.4(IO3)
TMS_SWDIO: CN12.2 CN17.7 R54.1 R55.1 U16.1(IO1)
TRACE_CLK: CN12.12 U9.1(IO1) ; port TRACE_CLK
TRACE_D0: CN12.14 R30.1 U7.5(IO4) ; port TRACE_D0
TRACE_D1: CN12.16 R31.1 U7.4(IO3) ; port TRACE_D1
TRACE_D2: CN12.18 U7.3(IO2) ; port TRACE_D2
TRACE_D3: CN12.20 U7.1(IO1) ; port TRACE_D3
NetCN17_11: CN17.11 R230.2 R232.1
NetCN17_17: CN17.17 R235.2
NetCN17_19: CN17.19 R236.2

Not connected (* = marked no-connect by the designer): CN12 7*

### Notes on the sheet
- JTAG & TRACE
- To disconnect JTAG connectors from target :
  - Remove 22R resistors
- PA13
- PA14
- PB3
- PA15
- PB4
- NRST
- (near CN12) TRACE CONNECTOR
- (near CN12) TRACE
- (near CN12) TMS/SWDIO
- (near CN12) TCK/SWCLK
- (near CN17) JTAG CONNECTOR
- (near CN17) JTAG
- (near CN17) JTRSTN
- KEY
- (near CN12) TDO/SWO
- (near CN12) TDI
- (near CN12) HOST_NRST
- (near CN12) TRACECLK
- (near CN12) TRACED0
- (near CN17) TDI
- (near CN17) TMS/SWDIO
- (near CN17) TCK/SWCLK
- (near CN17) TDO/SWO
- (near CN12) TRACED1
- (near CN12) TRACED2
- (near CN12) TRACED3
- (near CN17) HOST_NRST
- (near CN17) TRGIN
- (near CN17) TRGOUT
- (near CN12) FTSH-110-01-L-DV
- PC12
- PE5
- PC10
- PC9
- PE2
- LIMITATIONS :
- See User Manual for more detail about muxing.
- JTAG_TDI exclusive with UCPD_CC1
- TRACE_D0/D1/D3 exclusive with SDIO_CK/D1/D2
- JTAG-JTDO exclusive with ADF1_CCK0
- TRACE_D3 exclusive with STMOD+-SPI
- JTAG-NJTRST exclusive with ADF1_SDIN0, COMP2 and STMOD+ SPI

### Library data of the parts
CN12 = MCD-00557: Header 10x2, 1.27mm, VR, CMS, Height 3.05mm; Part_Type: Connector; Manufacturer_Part_Number: FTSH-110-01-L-DV; Manufacturer: SAMTEC; Alternate_Manufacturer_Part_Number: P127B-2*10MGF-079-1E7A; Alternate_Manufacturer: JIUBABA; Provided_By: Subcon; Initial_Board_Reference: MB1331
CN17 = MCD-01058: Header, 2.54mm, 10x2, VR, TH, Height 9.1mm/3,1mm; Part_Type: Connector; Manufacturer: SAMTEC; Alternate_Manufacturer_Part_Number: CH87-20-2-V-1-00; Alternate_Manufacturer: CVILUX; Provided_By: Subcon; Initial_Board_Reference: MB1331
R30 R31 = MCD-00056: as R77 on sheet FDCAN_RS232
R40 R46 R53 R54 R58 R62 = MCD-00066: Resistor,22R,0603,1%,1/10W; Manufacturer_Part_Number: RC0603FR-0722RL; Manufacturer: YAGEO; Provided_By: Subcon; Initial_Board_Reference: MB1274
R41 R47 R55 R61 R63 = MCD-00070: Resistor,1K,0603,1%,1/10W; Manufacturer_Part_Number: RC0603FR-071KL; Manufacturer: YAGEO; Provided_By: Subcon; Initial_Board_Reference: MB1274
R230 R232 R235 R236 = MCD-00220: as R64 on sheet BOARD_PWR
U7 U16 = MCD-00136: Dual Transil array for ESD protection; Manufacturer: STMICROELECTRONICS; Part_Type: Diode; Provided_By: Subcon; ECCN_US: EAR99; ECCN_EU: NEC; Initial_Board_Reference: MB1262
U9 U11 U13 = MCD-00170: ESD protection 6V1; Part_Type: Diode; Manufacturer: STMICROELECTRONICS; ECCN_US: EAR99; ECCN_EU: NEC; Provided_By: Subcon; Initial_Board_Reference: MB1274

## Sheet MCU_CLOCK_&_RESET.SchDoc: MCU CLOCK & RESET
size A4; Date: Not used; ApprovedBy: Not used; CheckedBy: Not used; Author: Not used; CompanyName: STMicroelectronics; DrawnBy: Not used; Engineer: Not used; Organization: Not used; Address1: Not used; Address2: Not used; Address3: Not used; Address4: Not used; DocumentNumber: 4; Revision: Not used; SheetNumber: 4; SheetTotal: 24
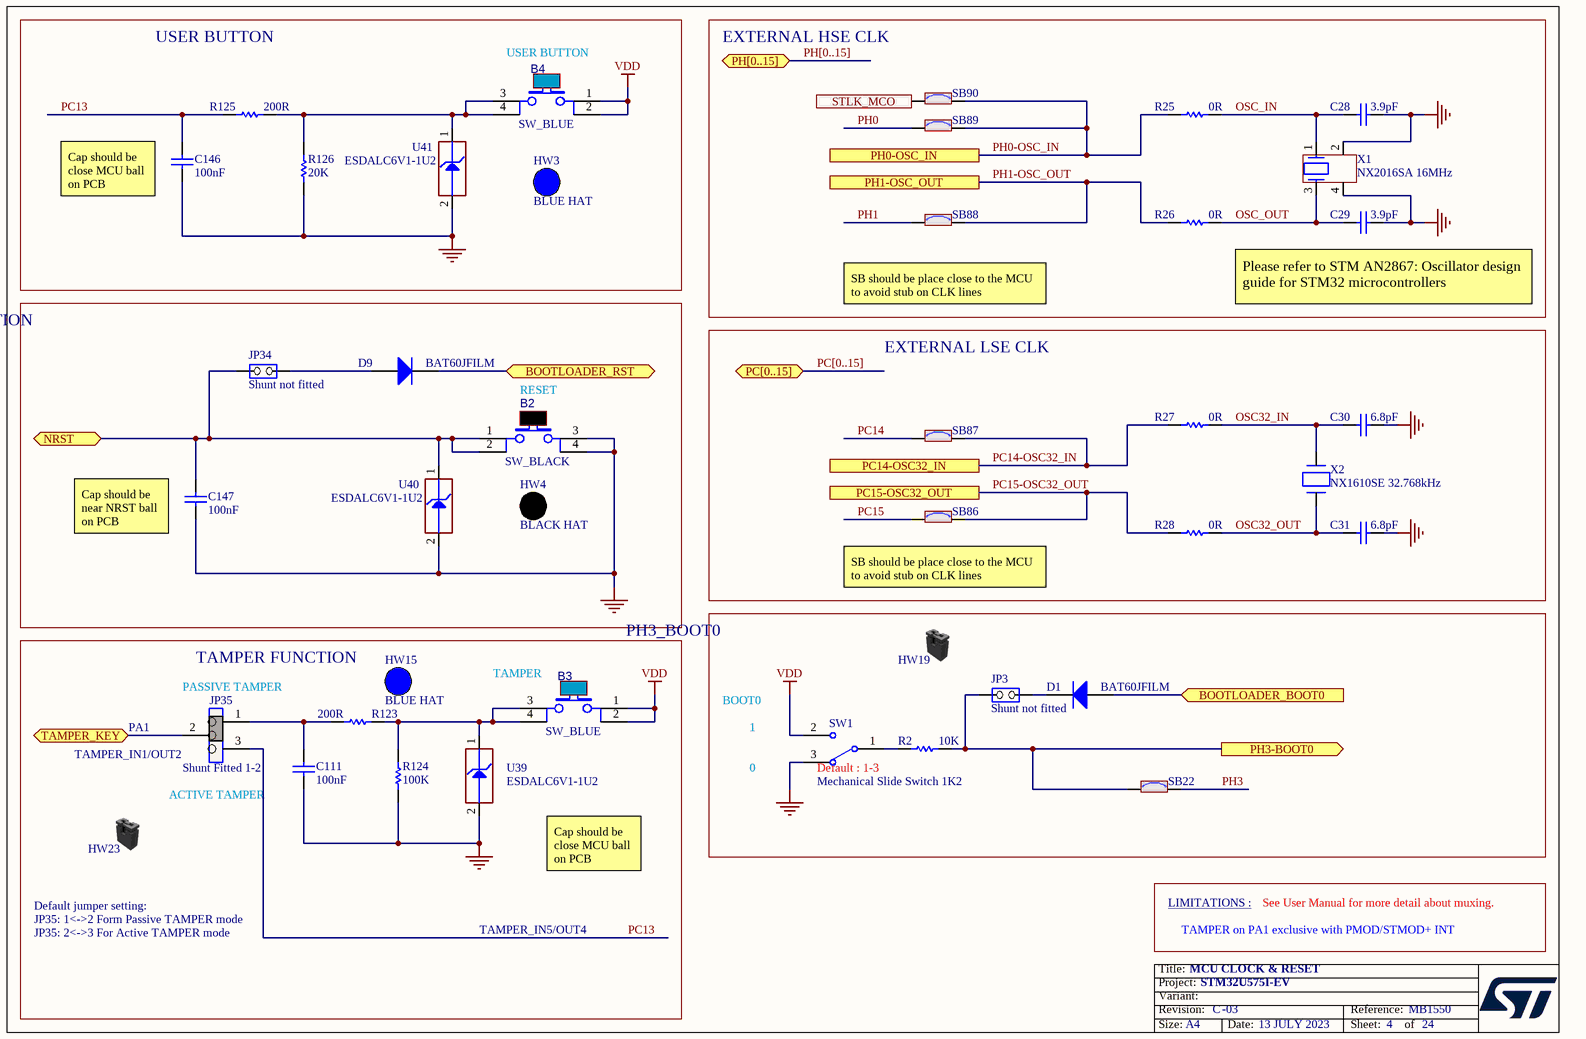
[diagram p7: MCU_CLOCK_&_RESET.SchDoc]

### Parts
B2  value SW_BLACK  [SWI_WEALTHMETAL_TD-0341_4P_BLACK]
B3  value SW_BLUE  [SWI_WEALTHMETAL_TD-0341_4P_BLUE]
B4  value SW_BLUE  [SWI_WEALTHMETAL_TD-0341_4P_BLUE]
C28  value 3.9pF  [C0402]  (hidden comment: Capacitor)
C29  value 3.9pF  [C0402]  (hidden comment: Capacitor)
C30  value 6.8pF  [C0402]  (hidden comment: Capacitor)
C31  value 6.8pF  [C0402]  (hidden comment: Capacitor)
C111  value 100nF  [C0402]
C146  value 100nF  [C0402]
C147  value 100nF  [C0402]
D1  value BAT60JFILM  [DIO_SOD323]
D9  value BAT60JFILM  [DIO_SOD323]
HW3  value BLUE HAT  (mechanical)
HW4  value BLACK HAT  (mechanical)
HW15  value BLUE HAT  (mechanical)
HW19  (no value)  (mechanical)
HW23  (no value)  (mechanical)
JP3  value Shunt not fitted  [CON_SAMTEC_TSW-102-07-G-S]
JP34  value Shunt not fitted  [CON_SAMTEC_TSW-102-07-G-S]
JP35  value Shunt Fitted 1-2  [CON_SAMTEC_TSW-103-07-F-S]
R2  value 10K  [R0603]
R25  value 0R  [R0402]
R26  value 0R  [R0402]
R27  value 0R  [R0402]
R28  value 0R  [R0402]
R123  value 200R  [R0603]
R124  value 100K  [R0603]
R125  value 200R  [R0603]
R126  value 20K  [R0603]
SB22  (no value)  [SOLDER-BRIDGE_R0603-0R]
SB86  (no value)  [SOLDER-BRIDGE_R0603-0R]
SB87  (no value)  [SOLDER-BRIDGE_R0603-0R]
SB88  (no value)  [SOLDER-BRIDGE_R0603-0R]
SB89  (no value)  [SOLDER-BRIDGE_R0603-0R]
SB90  (no value)  [SOLDER-BRIDGE_R0603-0R]
SW1  value Mechanical Slide Switch 1K2  [SWI_EAO_09-03290-01_EXTENDED_STRAIGHT_BLACK]  (hidden comment: SW_MECA_1K2)
U39  value ESDALC6V1-1U2  [ESD_ST0201]
U40  value ESDALC6V1-1U2  [ESD_ST0201]
U41  value ESDALC6V1-1U2  [ESD_ST0201]
X1  value NX2016SA 16MHz  [CRY_NX2016SA_4P]  (hidden comment: XTAL_4_PINS)
X2  value NX1610SE 32.768kHz  [CRY_NX1610SE_2P]  (hidden comment: XTAL_2_PINS)

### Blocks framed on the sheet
USER BUTTON: B4 C146 HW3 R125 R126 U41
EXTERNAL HSE CLK: C28 C29 R25 R26 SB88-SB90 X1
RESET FUNCTION: B2 C147 D9 HW4 JP34 U40
EXTERNAL LSE CLK: C30 C31 R27 R28 SB86 SB87 X2
PH3_BOOT0: D1 HW19 JP3 R2 SB22 SW1
TAMPER FUNCTION: B3 C111 HW15 HW23 JP35 R123 R124 U39

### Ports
BOOTLOADER_BOOT0 (in), BOOTLOADER_RST (bidir), NRST (bidir), PC14-OSC32_IN, PC15-OSC32_OUT, PC[0..15] (bidir), PH0-OSC_IN, PH1-OSC_OUT, PH3-BOOT0 (out), PH[0..15] (bidir), STLK_MCO, TAMPER_KEY (bidir)

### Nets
GND: B2.3 B2.4 C28.2 C29.2 C30.2 C31.2 C111.1 C146.1 C147.1 R124.1 R126.1 SW1.3 U39.2(GND) U40.2(GND) U41.2(GND) X1.2 X1.4
VDD: B3.1 B3.2 B4.1 B4.2 SW1.2
BOOTLOADER_BOOT0: D1.1(A) ; port BOOTLOADER_BOOT0
BOOTLOADER_RST: D9.2(K) ; port BOOTLOADER_RST
NRST: B2.1 B2.2 C147.2 JP34.1(COMMON) U40.1(IO1) ; port NRST
OSC32_IN: C30.1 R27.2 X2.2(X2)
OSC32_OUT: C31.1 R28.2 X2.1(X1)
OSC_IN: C28.1 R25.2 X1.1
OSC_OUT: C29.1 R26.2 X1.3
PC13: C146.2 JP35.3 R125.1
PC14: SB87.1
PC14-OSC32_IN: R27.1 SB87.2 ; port PC14-OSC32_IN
PC15: SB86.1
PC15-OSC32_OUT: R28.1 SB86.2 ; port PC15-OSC32_OUT
PH0: SB89.1
PH0-OSC_IN: R25.1 SB89.2 SB90.2 ; port PH0-OSC_IN
PH1: SB88.1
PH1-OSC_OUT: R26.1 SB88.2 ; port PH1-OSC_OUT
PH3: SB22.2
PH3-BOOT0: JP3.1(COMMON) R2.2 SB22.1 ; port PH3-BOOT0
STLK_MCO: SB90.1 ; port STLK_MCO
TAMPER_KEY: JP35.2 ; port TAMPER_KEY
NetB3_3: B3.3 B3.4 R123.2 R124.2 U39.1(IO1)
NetB4_3: B4.3 B4.4 R125.2 R126.2 U41.1(IO1)
NetC111_2: C111.2 JP35.1 R123.1
NetD1_2: D1.2(K) JP3.2(NO)
NetD9_1: D9.1(A) JP34.2(NO)
NetR2_1: R2.1 SW1.1

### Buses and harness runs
bus PC[0..15] = port PC[0..15]
bus PH[0..15] = port PH[0..15]

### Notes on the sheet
- (near B4) USER BUTTON
- (near C146) Cap should be close MCU ball on PCB
- (near SB88) SB should be place close to the MCU to avoid stub on CLK lines
- Please refer to STM AN2867: Oscillator design guide for STM32 microcontrollers
- (near B2) RESET
- (near C147) Cap should be near NRST ball on PCB
- SB should be place close to the MCU to avoid stub on CLK lines
- (near JP35) PASSIVE TAMPER
- (near B3) TAMPER
- BOOT0
- TAMPER_IN1/OUT2
- PA1
- 1
- 0
- (near SW1) Default : 1-3
- ACTIVE TAMPER
- Cap should be close MCU ball on PCB
- LIMITATIONS :
- See User Manual for more detail about muxing.
- Default jumper setting:
  JP35: 1<->2 Form Passive TAMPER mode
  JP35: 2<->3 For Active TAMPER mode
- TAMPER_IN5/OUT4
- TAMPER on PA1 exclusive with PMOD/STMOD+ INT

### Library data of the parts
B2 = MCD-00001: Non-Open Push-Button 0.1A 24V; Manufacturer_Part_Number: TD0341X-G01-BLA; Manufacturer: WEALTHMETAL; Part_Type: Misc; Provided_By: Subcon; Initial_Board_Reference: MB1274
B3 B4 = MCD-00002: Non-Open Push-Button 0.1A 24V; Manufacturer_Part_Number: TD0341X-G01-BLU; Manufacturer: WEALTHMETAL; Part_Type: Misc; Provided_By: Subcon; Initial_Board_Reference: MB1274
C28 C29 = MCD-00556: Capacitor, MLCC, 3.9pF, 50V, NPO, +-0.25pF, 0402, T=0,5mm; Manufacturer_Part_Number: CC0402CRNPO9BN3R9; Manufacturer: YAGEO; Provided_By: SUBCO
C30 C31 = MCD-00674: Capacitor, MLCC, 6.8pF, 50V, NPO, +/-0.25pF, 0402, T=0.5mm; Part_Preference: Recommended; Manufacturer: YAGEO; Manufacturer_Part_Number: CC0402CRNPO9BN6R8; Component_Country_Of_Origin: China; ShowFields: YES; ID: 3068
C111 C146 C147 = MCD-00006: as C50 on sheet BOARD_PWR
D1 D9 = MCD-00034: BAT60JFILM; Manufacturer: STMICROELECTRONICS; Part_Type: Diode; ECCN_US: EAR99; ECCN_EU: NEC; Provided_By: Subcon; Initial_Board_Reference: MB1274
HW3 HW15 = MCD-00634: Blue Hat for switch TD0341X-G01-BLU; Part_Type: Mechanical; Manufacturer_Part_Number: 988.16.09.3.00002_SH-517; Manufacturer: JIUBABA; Provided_By: Subcon; Initial_Board_Reference: MB1319
HW4 = MCD-00635: Black Hat for switch TD0341X-G01-BLA; Part_Type: Mechanical; Manufacturer_Part_Number: 988.16.09.3.00003_SH-517; Manufacturer: JIUBABA; Provided_By: Subcon; Initial_Board_Reference: MB1319
HW19 HW23 = MCD-00043: as HW10 on sheet FDCAN_RS232
JP3 JP34 = MCD-00045: as JP27 on sheet FDCAN_RS232
JP35 = MCD-00684: as JP26 on sheet FDCAN_RS232
R2 = MCD-00220: as R64 on sheet BOARD_PWR
R25-R28 = MCD-00052: Resistor,0R,0402,5%,1/16W; Manufacturer_Part_Number: RC0402JR-070RL; Manufacturer: YAGEO; Provided_By: Subcon; Initial_Board_Reference: MB1274
R123 R125 = MCD-00418: Resistor,200R,0603,1%,1/10W; Manufacturer_Part_Number: RC0603FR-07200RL; Manufacturer: YAGEO; Provided_By: SUBCO; ECCN_US: EAR99; ECCN_EU: NEC
R124 = MCD-00223: as R167 on sheet FDCAN_RS232
R126 = MCD-00422: as R56 on sheet BOARD_PWR
SB22 SB86-SB90 = MCD-00071: as SB3 on sheet BOARD_PWR
SW1 = MCD-00566: Mechanical Slide Switches 1K2 BLK ACT GOLD STRT MNT; Part_Type: Misc; Manufacturer_Part_Number: 09.03290.01; Manufacturer: EAO; Provided_By: SUBCO; Initial_Board_Reference: MB1331; Item Type: Item; Path: ws/MCD_ApplicationBoards/Lists/MCDPARTSdatabase
U39-U41 = MCD-00170: as U9 on sheet JTAG_TRACE
X1 = MCD-01476: Crystal 16 MHz, 8pF, -+20 PPM, R=200Ω, SMD; Part_Type: Crystal_Osc; Manufacturer_Part_Number: NX2016SA 16 MHz EXS00A-CS07826; Manufacturer: NDK; Provided_By: ST; Initial_Board_Reference: MB1373; Item Type: Item; Path: ws/MCD_ApplicationBoards/Lists/MCDPARTSdatabase
X2 = MCD-02291: Crystal 32.768kHz, 9pF, -+20ppm, 70Kohm max, SMD; Part_Type: Crystal_Osc; Manufacturer_Part_Number: NX1610SE 32.768KHz EXS00A-MU01499; Manufacturer: NDK; Part_Preference: Recommended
